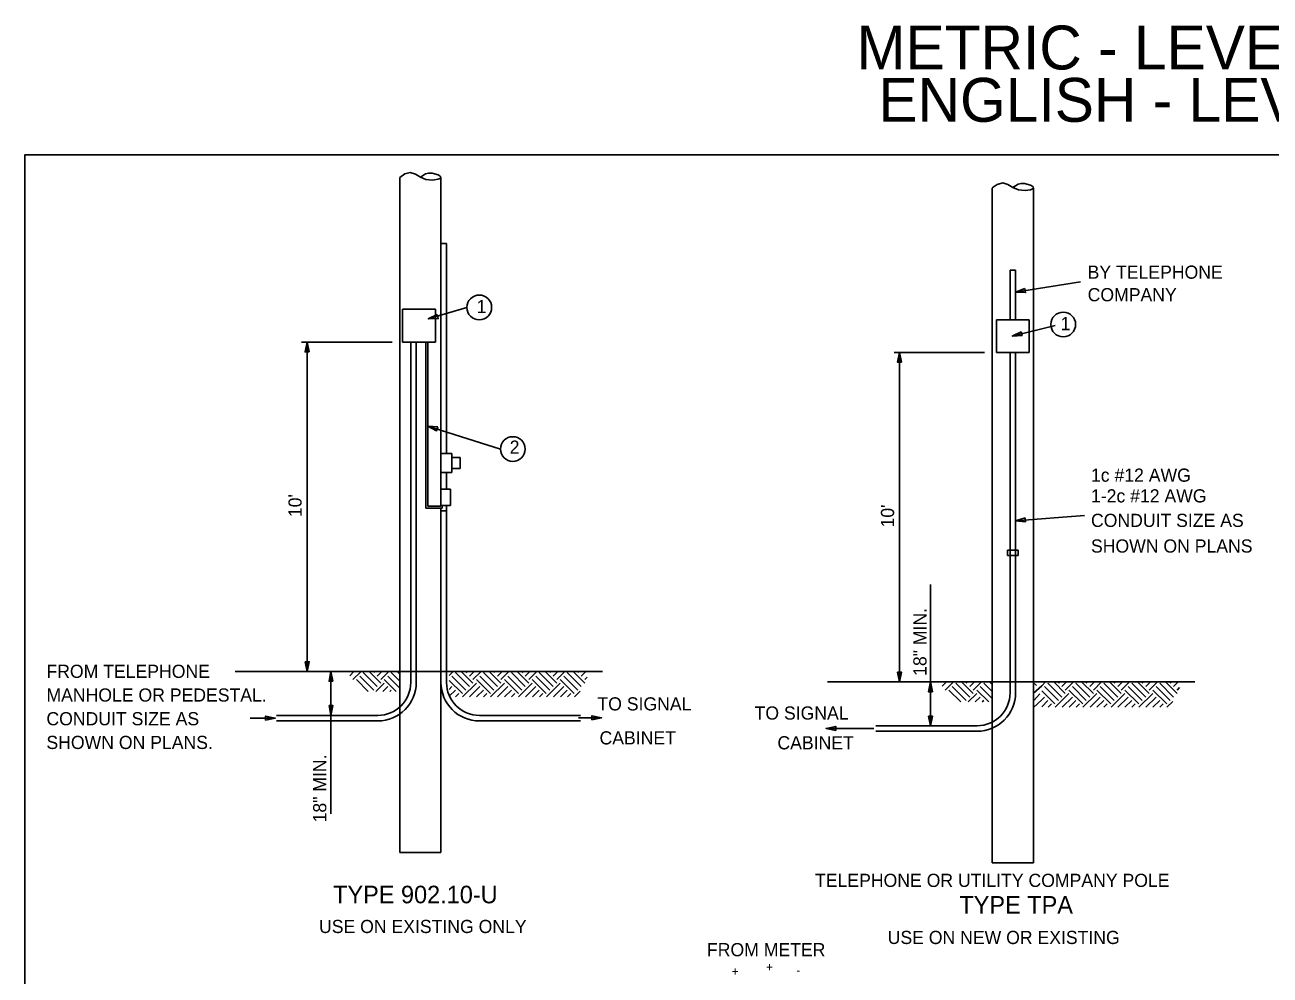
# Model space of a CAD drawing. Extents: x -439.1 to -407.9, y -458.1 to -436.2.
# Drawn here: x -439.11 to -424.94, y -447.02 to -436.2 of the extents above; entities that cross this region are included whole.
import ezdxf

# ---------------------------------------------------------------- set-up
doc = ezdxf.new("R2010")
doc.units = 0
for name, color, linetype in [('Draft_Named_Boundary', 7, 'Continuous'), ('Level 4', 7, 'Continuous'), ('Level 45', 7, 'Continuous'), ('Level 46', 7, 'Continuous')]:
    doc.layers.add(name, color=color, linetype=linetype)

msp = doc.modelspace()

# ---------------------------------------------------------------- linework, layer by layer
at = {"layer": 'Draft_Named_Boundary'}
msp.add_lwpolyline([(-439.109, -458.051), (-407.859, -458.051), (-407.859, -437.676), (-439.109, -437.676)], close=True, dxfattribs=at)
at = {"layer": 'Level 4'}
for p, q in [((-434.842, -437.936), (-434.842, -443.561)), ((-434.373, -437.936), (-434.373, -441.679)), ((-428.098, -438.055), (-428.098, -443.68)), ((-427.629, -438.055), (-427.629, -443.68)), ((-434.311, -438.686), (-434.373, -438.686)), ((-434.311, -438.686), (-434.311, -441.077)), ((-427.895, -438.992), (-427.895, -439.555)), ((-427.895, -438.992), (-427.832, -438.992)), ((-427.832, -438.992), (-427.832, -439.555)), ((-427.832, -439.24), (-427.095, -439.125)), ((-434.811, -439.436), (-434.811, -439.811)), ((-434.436, -439.436), (-434.811, -439.436)), ((-434.517, -439.546), (-434.078, -439.415)), ((-434.436, -439.436), (-434.436, -439.811)), ((-427.676, -439.555), (-428.051, -439.555)), ((-428.051, -439.555), (-428.051, -439.93)), ((-427.871, -439.741), (-427.382, -439.619)), ((-427.676, -439.555), (-427.676, -439.93)), ((-434.929, -439.811), (-435.959, -439.811)), ((-435.896, -443.561), (-435.896, -439.811)), ((-434.436, -439.811), (-434.811, -439.811)), ((-434.717, -439.811), (-434.717, -443.686)), ((-434.655, -439.811), (-434.655, -443.686)), ((-434.545, -439.811), (-434.545, -441.702)), ((-434.522, -439.811), (-434.522, -441.679)), ((-428.185, -439.929), (-429.215, -439.929)), ((-429.152, -443.679), (-429.152, -439.929)), ((-427.676, -439.93), (-428.051, -439.93)), ((-427.895, -439.93), (-427.895, -443.805)), ((-427.832, -439.93), (-427.832, -443.805)), ((-434.521, -440.766), (-433.696, -441.028)), ((-434.373, -441.077), (-434.248, -441.077)), ((-434.248, -441.296), (-434.248, -441.077)), ((-434.248, -441.124), (-434.158, -441.124)), ((-434.155, -441.245), (-434.155, -441.128)), ((-434.373, -441.296), (-434.373, -441.483)), ((-434.373, -441.296), (-434.248, -441.296)), ((-434.311, -441.296), (-434.311, -441.483)), ((-434.311, -441.296), (-434.311, -441.483)), ((-434.248, -441.249), (-434.158, -441.249)), ((-434.373, -441.483), (-434.264, -441.483)), ((-434.264, -441.483), (-434.264, -441.671)), ((-434.545, -441.702), (-434.358, -441.702)), ((-434.522, -441.679), (-434.373, -441.679)), ((-434.373, -441.671), (-434.264, -441.671)), ((-434.373, -441.702), (-434.373, -443.561)), ((-434.373, -441.733), (-434.311, -441.733)), ((-434.358, -441.671), (-434.358, -441.702)), ((-434.311, -441.671), (-434.311, -443.686)), ((-427.832, -441.844), (-427.047, -441.786)), ((-427.801, -442.18), (-427.926, -442.18)), ((-427.926, -442.18), (-427.926, -442.242)), ((-427.801, -442.18), (-427.801, -442.242)), ((-427.801, -442.242), (-427.926, -442.242)), ((-428.802, -444.18), (-428.802, -442.569)), ((-436.717, -443.561), (-432.535, -443.561)), ((-435.625, -443.561), (-435.625, -445.181)), ((-435.412, -443.61), (-435.363, -443.561)), ((-435.376, -443.654), (-435.283, -443.561)), ((-435.137, -443.773), (-435.296, -443.614)), ((-435.098, -443.733), (-435.257, -443.574)), ((-435.058, -443.694), (-435.19, -443.561)), ((-435.137, -443.574), (-435.124, -443.561)), ((-435.098, -443.614), (-435.045, -443.561)), ((-435.058, -443.654), (-434.965, -443.561)), ((-434.842, -443.751), (-434.978, -443.614)), ((-434.842, -443.671), (-434.938, -443.574)), ((-434.842, -443.592), (-434.872, -443.561)), ((-434.842, -443.561), (-434.842, -445.624)), ((-434.373, -443.561), (-434.373, -445.624)), ((-434.279, -443.605), (-434.235, -443.561)), ((-434.089, -443.773), (-434.248, -443.614)), ((-434.049, -443.733), (-434.208, -443.574)), ((-434.009, -443.694), (-434.142, -443.561)), ((-434.089, -443.574), (-434.076, -443.561)), ((-434.049, -443.614), (-433.996, -443.561)), ((-434.009, -443.654), (-433.917, -443.561)), ((-433.771, -443.773), (-433.93, -443.614)), ((-433.731, -443.733), (-433.89, -443.574)), ((-433.691, -443.694), (-433.824, -443.561)), ((-433.771, -443.574), (-433.758, -443.561)), ((-433.731, -443.614), (-433.678, -443.561)), ((-433.691, -443.654), (-433.599, -443.561)), ((-433.453, -443.773), (-433.612, -443.614)), ((-433.413, -443.733), (-433.572, -443.574)), ((-433.373, -443.694), (-433.506, -443.561)), ((-433.453, -443.574), (-433.439, -443.561)), ((-433.413, -443.614), (-433.36, -443.561)), ((-433.373, -443.654), (-433.28, -443.561)), ((-433.134, -443.773), (-433.294, -443.614)), ((-433.095, -443.733), (-433.254, -443.574)), ((-433.055, -443.694), (-433.187, -443.561)), ((-433.134, -443.574), (-433.121, -443.561)), ((-433.095, -443.614), (-433.042, -443.561)), ((-433.055, -443.654), (-432.962, -443.561)), ((-432.816, -443.773), (-432.975, -443.614)), ((-432.776, -443.733), (-432.936, -443.574)), ((-432.737, -443.694), (-432.869, -443.561)), ((-432.816, -443.574), (-432.803, -443.561)), ((-432.776, -443.614), (-432.724, -443.561)), ((-432.737, -443.654), (-432.71, -443.627)), ((-435.2, -443.79), (-435.336, -443.654)), ((-435.115, -443.79), (-435.018, -443.694)), ((-435.035, -443.79), (-434.978, -443.733)), ((-434.882, -443.79), (-435.018, -443.654)), ((-434.955, -443.79), (-434.938, -443.773)), ((-434.129, -443.813), (-434.279, -443.663)), ((-434.279, -443.765), (-434.248, -443.733)), ((-434.279, -443.844), (-434.208, -443.773)), ((-434.127, -443.851), (-433.97, -443.694)), ((-434.047, -443.851), (-433.93, -443.733)), ((-433.811, -443.813), (-433.97, -443.654)), ((-433.968, -443.851), (-433.89, -443.773)), ((-433.809, -443.851), (-433.651, -443.694)), ((-433.729, -443.851), (-433.612, -443.733)), ((-433.492, -443.813), (-433.651, -443.654)), ((-433.65, -443.851), (-433.572, -443.773)), ((-433.49, -443.851), (-433.333, -443.694)), ((-433.411, -443.851), (-433.294, -443.733)), ((-433.174, -443.813), (-433.333, -443.654)), ((-433.331, -443.851), (-433.254, -443.773)), ((-433.172, -443.851), (-433.015, -443.694)), ((-433.093, -443.851), (-432.975, -443.733)), ((-432.856, -443.813), (-433.015, -443.654)), ((-433.013, -443.851), (-432.936, -443.773)), ((-432.854, -443.851), (-432.787, -443.784)), ((-429.973, -443.68), (-425.791, -443.68)), ((-428.668, -443.728), (-428.619, -443.679)), ((-428.632, -443.772), (-428.539, -443.679)), ((-428.456, -443.908), (-428.592, -443.772)), ((-428.393, -443.891), (-428.553, -443.732)), ((-428.354, -443.852), (-428.513, -443.693)), ((-428.314, -443.812), (-428.446, -443.679)), ((-428.393, -443.693), (-428.38, -443.679)), ((-428.354, -443.732), (-428.301, -443.679)), ((-428.314, -443.772), (-428.221, -443.679)), ((-428.138, -443.908), (-428.274, -443.772)), ((-428.098, -443.869), (-428.234, -443.732)), ((-428.098, -443.789), (-428.195, -443.693)), ((-428.098, -443.71), (-428.128, -443.679)), ((-428.098, -443.68), (-428.098, -445.742)), ((-427.595, -443.722), (-427.634, -443.682)), ((-427.629, -443.68), (-427.629, -445.742)), ((-427.535, -443.724), (-427.628, -443.807)), ((-427.535, -443.724), (-427.491, -443.679)), ((-427.385, -443.931), (-427.535, -443.781)), ((-427.345, -443.891), (-427.504, -443.732)), ((-427.305, -443.852), (-427.464, -443.693)), ((-427.266, -443.812), (-427.398, -443.679)), ((-427.345, -443.693), (-427.332, -443.679)), ((-427.305, -443.732), (-427.252, -443.679)), ((-427.266, -443.772), (-427.173, -443.679)), ((-427.067, -443.931), (-427.226, -443.772)), ((-427.027, -443.891), (-427.186, -443.732)), ((-426.987, -443.852), (-427.146, -443.693)), ((-426.947, -443.812), (-427.08, -443.679)), ((-427.027, -443.693), (-427.014, -443.679)), ((-426.987, -443.732), (-426.934, -443.679)), ((-426.947, -443.772), (-426.855, -443.679)), ((-426.748, -443.931), (-426.908, -443.772)), ((-426.709, -443.891), (-426.868, -443.732)), ((-426.669, -443.852), (-426.828, -443.693)), ((-426.629, -443.812), (-426.762, -443.679)), ((-426.709, -443.693), (-426.696, -443.679)), ((-426.669, -443.732), (-426.616, -443.679)), ((-426.629, -443.772), (-426.536, -443.679)), ((-426.43, -443.931), (-426.589, -443.772)), ((-426.39, -443.891), (-426.55, -443.732)), ((-426.351, -443.852), (-426.51, -443.693)), ((-426.311, -443.812), (-426.443, -443.679)), ((-426.39, -443.693), (-426.377, -443.679)), ((-426.351, -443.732), (-426.298, -443.679)), ((-426.311, -443.772), (-426.218, -443.679)), ((-426.112, -443.931), (-426.271, -443.772)), ((-426.072, -443.891), (-426.231, -443.732)), ((-426.033, -443.852), (-426.192, -443.693)), ((-425.993, -443.812), (-426.125, -443.679)), ((-426.072, -443.693), (-426.059, -443.679)), ((-426.033, -443.732), (-425.98, -443.679)), ((-425.993, -443.772), (-425.966, -443.745)), ((-434.206, -443.851), (-434.169, -443.813)), ((-433.888, -443.851), (-433.85, -443.813)), ((-433.57, -443.851), (-433.532, -443.813)), ((-433.252, -443.851), (-433.214, -443.813)), ((-432.934, -443.851), (-432.896, -443.813)), ((-428.371, -443.908), (-428.274, -443.812)), ((-428.291, -443.908), (-428.234, -443.852)), ((-428.211, -443.908), (-428.195, -443.891)), ((-427.535, -443.883), (-427.628, -443.972)), ((-427.555, -443.814), (-427.621, -443.886)), ((-427.535, -443.883), (-427.504, -443.852)), ((-427.535, -443.962), (-427.464, -443.891)), ((-427.383, -443.969), (-427.226, -443.812)), ((-427.303, -443.969), (-427.186, -443.852)), ((-427.224, -443.969), (-427.146, -443.891)), ((-427.065, -443.969), (-426.908, -443.812)), ((-426.985, -443.969), (-426.868, -443.852)), ((-426.906, -443.969), (-426.828, -443.891)), ((-426.746, -443.969), (-426.589, -443.812)), ((-426.667, -443.969), (-426.55, -443.852)), ((-426.587, -443.969), (-426.51, -443.891)), ((-426.428, -443.969), (-426.271, -443.812)), ((-426.349, -443.969), (-426.231, -443.852)), ((-426.269, -443.969), (-426.192, -443.891)), ((-426.11, -443.969), (-426.043, -443.902)), ((-436.245, -444.061), (-435.092, -444.061)), ((-432.783, -444.061), (-433.936, -444.061)), ((-427.462, -443.969), (-427.425, -443.931)), ((-427.144, -443.969), (-427.106, -443.931)), ((-426.826, -443.969), (-426.788, -443.931)), ((-426.508, -443.969), (-426.47, -443.931)), ((-426.19, -443.969), (-426.152, -443.931)), ((-436.26, -444.092), (-436.545, -444.092)), ((-436.245, -444.124), (-435.092, -444.124)), ((-432.783, -444.124), (-433.936, -444.124)), ((-432.545, -444.088), (-432.809, -444.09)), ((-429.446, -444.21), (-429.989, -444.21)), ((-429.422, -444.18), (-428.27, -444.18)), ((-429.422, -444.242), (-428.27, -444.242)), ((-434.842, -445.624), (-434.373, -445.624)), ((-428.098, -445.742), (-427.629, -445.742))]:
    msp.add_line(p, q, dxfattribs=at)
for points in [[(-434.842, -437.936), (-434.786, -437.895), (-434.723, -437.879), (-434.663, -437.897), (-434.606, -437.93), (-434.544, -437.958), (-434.468, -437.966), (-434.406, -437.956), (-434.383, -437.948), (-434.373, -437.936), (-434.381, -437.921), (-434.405, -437.906), (-434.475, -437.886), (-434.514, -437.886), (-434.548, -437.895), (-434.606, -437.93)], [(-428.098, -438.054), (-428.042, -438.014), (-427.979, -437.997), (-427.919, -438.015), (-427.862, -438.048), (-427.8, -438.076), (-427.724, -438.084), (-427.662, -438.075), (-427.639, -438.066), (-427.629, -438.054), (-427.637, -438.039), (-427.661, -438.024), (-427.731, -438.004), (-427.77, -438.004), (-427.804, -438.013), (-427.862, -438.048)]]:
    msp.add_lwpolyline(points, dxfattribs=at)
for points in [[(-427.726, -439.2), (-427.832, -439.24), (-427.719, -439.246)], [(-434.415, -439.497), (-434.517, -439.546), (-434.404, -439.542)], [(-435.873, -439.922), (-435.896, -439.811), (-435.919, -439.922)], [(-427.769, -439.692), (-427.871, -439.741), (-427.758, -439.736)], [(-429.129, -440.04), (-429.152, -439.929), (-429.175, -440.04)], [(-434.409, -440.776), (-434.521, -440.766), (-434.422, -440.82)], [(-427.723, -441.813), (-427.832, -441.844), (-427.72, -441.858)], [(-435.919, -443.45), (-435.896, -443.561), (-435.873, -443.45)], [(-435.602, -443.672), (-435.625, -443.561), (-435.647, -443.672)], [(-429.175, -443.569), (-429.152, -443.679), (-429.129, -443.569)], [(-428.779, -443.791), (-428.802, -443.68), (-428.825, -443.791)], [(-436.37, -444.115), (-436.26, -444.092), (-436.37, -444.069)], [(-435.647, -443.95), (-435.625, -444.061), (-435.602, -443.95)], [(-432.655, -444.112), (-432.545, -444.088), (-432.655, -444.066)], [(-428.825, -444.069), (-428.802, -444.18), (-428.779, -444.069)], [(-429.88, -444.233), (-429.99, -444.21), (-429.88, -444.187)]]:
    msp.add_lwpolyline(points, close=True, dxfattribs=at)
for centre in [(-433.937, -439.415), (-427.29, -439.609), (-433.555, -441.028)]:
    msp.add_circle(centre, 0.141, dxfattribs=at)
for centre, radius, start, end in [((-434.158, -441.128), 0.00391, 0, 90), ((-434.158, -441.245), 0.00391, 270, 0), ((-435.092, -443.686), 0.375, 270, 0), ((-435.092, -443.686), 0.438, 270, 360), ((-433.935, -443.686), 0.438, 180, 270), ((-433.935, -443.686), 0.375, 180, 270), ((-428.27, -443.804), 0.438, 270, 360), ((-428.27, -443.804), 0.375, 270, 0)]:
    msp.add_arc(centre, radius, start, end, dxfattribs=at)

# ---------------------------------------------------------------- texts
for s, height, p in [('BY TELEPHONE', 0.15, (-427.012, -439.088)), ('COMPANY', 0.15, (-427.012, -439.345)), ('1', 0.15, (-433.967, -439.48)), ('1', 0.15, (-427.32, -439.674)), ('2', 0.15, (-433.591, -441.081)), ('1c #12 AWG', 0.15, (-426.974, -441.4)), ('1-2c #12 AWG', 0.15, (-426.974, -441.636)), ('CONDUIT SIZE AS', 0.15, (-426.974, -441.915)), ('SHOWN ON PLANS', 0.15, (-426.974, -442.207)), ('FROM TELEPHONE ', 0.15, (-438.864, -443.634)), ('MANHOLE OR PEDESTAL. ', 0.15, (-438.864, -443.904)), ('TO SIGNAL', 0.15, (-432.592, -444.005)), ('CONDUIT SIZE AS ', 0.15, (-438.864, -444.174)), ('TO SIGNAL', 0.15, (-430.803, -444.109)), ('SHOWN ON PLANS.', 0.15, (-438.864, -444.444)), ('CABINET', 0.15, (-432.568, -444.392)), ('CABINET', 0.15, (-430.543, -444.448)), ('TELEPHONE OR UTILITY COMPANY POLE', 0.15, (-430.115, -446.015)), ('TYPE 902.10-U', 0.2, (-435.601, -446.201)), ('TYPE TPA', 0.2, (-428.472, -446.319)), ('USE ON EXISTING ONLY', 0.15, (-435.761, -446.54)), ('USE ON NEW OR EXISTING', 0.15, (-429.288, -446.665)), ('FROM METER', 0.15, (-431.345, -446.804)), ('+', 0.1, (-430.672, -446.976)), ('+', 0.1, (-431.064, -447.025)), ('-', 0.1, (-430.328, -447.013))]:
    msp.add_text(s, height=height, dxfattribs=at).set_placement(p)
for s, p in [("10'", (-435.959, -441.803)), ("10'", (-429.215, -441.921)), ('18" MIN.', (-428.846, -443.611)), ('18" MIN.', (-435.678, -445.28))]:
    msp.add_text(s, height=0.15, rotation=90, dxfattribs=at).set_placement(p)
at = {"layer": 'Level 45'}
msp.add_text('ENGLISH - LEVEL 45 - RED', height=0.5, dxfattribs=at).set_placement((-429.393, -437.301))
at = {"layer": 'Level 46'}
msp.add_text('METRIC - LEVEL 46 - GREEN', height=0.5, dxfattribs=at).set_placement((-429.642, -436.705))

doc.saveas('drawing.dxf')
